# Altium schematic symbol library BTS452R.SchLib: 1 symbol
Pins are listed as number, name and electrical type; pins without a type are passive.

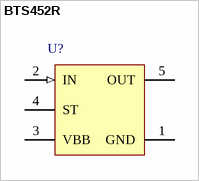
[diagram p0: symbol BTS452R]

## BTS452R
designator U?
Smart High-Side Power Switch, 1 Channel, 1.3 A Load Current, -40 to 150 degC, PG-TO252-5-11, Reel, Green; Manufacturer: Infineon; PartNumber: BTS452R; Channels: 1; Green: TRUE; Group: Automotive Qualified; Load Current (typ): 1.3 A; Ptot (max): 41.6 mW; Recommended Operating Voltage Max.: 52 V; Recommended Operating Voltage Min.: 6 V; RON @ 25degreesC: 150 mOhm; RON(max) @ 150degreesC: 270 mOhm; toff (max): 200 us; ton (max): 180 us
footprint INF-PG-TO252-5-11_N (DPAK, 5-Leads, Body 6.5x6.12mm, Pitch 1.14mm, IPC Medium Density)
footprint INF-PG-TO252-5-11_L (DPAK, 5-Leads, Body 6.5x6.12mm, Pitch 1.14mm, IPC High Density)
footprint INF-PG-TO252-5-11_M (DPAK, 5-Leads, Body 6.5x6.12mm, Pitch 1.14mm, IPC Low Density)
pins: 1 GND (power) "Logic ground.", 2 IN (in) "Input, activates the power switch in case of logical signal.", 3 VBB (power) "Positive power supply voltage, the tab is shorted to this pin", 4 ST (oc) "Diagnostic feedback", 5 OUT (power) "Output to the load."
